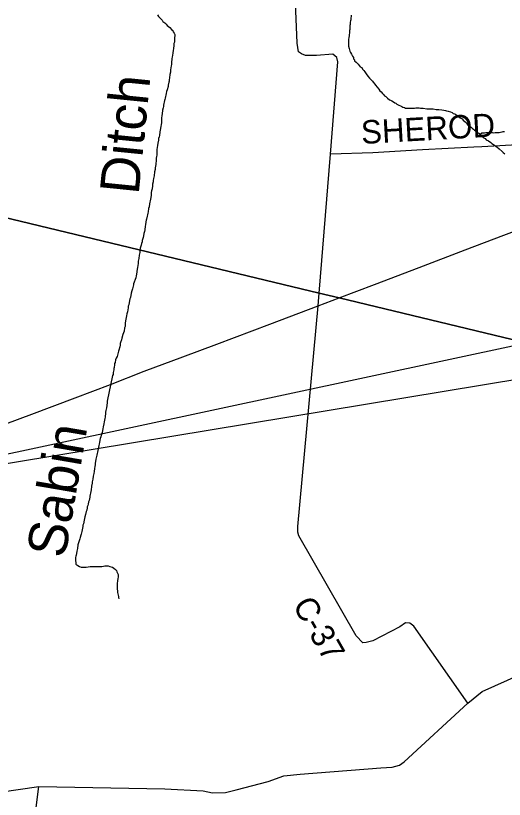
# Model space of a CAD drawing. Extents: x 0.4 to 34.4, y -2.1 to 19.9.
# Drawn here: x 7.097 to 8.281, y 14.658 to 16.558 of the extents above; entities that cross this region are included whole.
import ezdxf

# ---------------------------------------------------------------- set-up
doc = ezdxf.new("R2010")
doc.units = 0
for name, color, linetype in [('GM_X_County_Road', 7, 'Continuous'), ('GM_X_County_Road_Text', 7, 'Continuous'), ('GM_X_Interstate_Route', 7, 'Continuous'), ('GM_X_Minor_River', 7, 'Continuous'), ('GM_X_Minor_River_Text', 7, 'Continuous'), ('GM_X_Township', 7, 'Continuous'), ('GM_X_Township_Road', 7, 'Continuous'), ('GM_X_Township_Road_Text', 7, 'Continuous'), ('SH_Data', 7, 'Continuous')]:
    doc.layers.add(name, color=color, linetype=linetype)

msp = doc.modelspace()

# ---------------------------------------------------------------- linework, layer by layer
at = {"layer": 'GM_X_County_Road'}
for points in [[(7.8306, 15.8648), (7.8323, 15.8856), (7.8597, 16.2224), (7.878, 16.4464), (7.8755, 16.4567), (7.8654, 16.4652), (7.8259, 16.4614), (7.7993, 16.4615), (7.7899, 16.4658), (7.7828, 16.4705), (7.779, 16.4915), (7.7421, 17.3856), (7.739, 17.402), (7.731, 17.4215), (7.7137, 17.448), (7.5422, 17.7657)], [(8.193, 14.8908), (8.0619, 15.0778), (8.0522, 15.0852), (8.042, 15.0854), (8.0278, 15.0758), (7.9626, 15.0421), (7.9462, 15.0379), (7.9382, 15.0373), (7.9226, 15.0546), (7.7835, 15.2967), (7.781, 15.3055), (7.7812, 15.3192), (7.8298, 15.8548), (7.8306, 15.8648), (7.8306, 15.8648)], [(7.058, 14.675), (7.1535, 14.6887), (7.4587, 14.6828), (7.5512, 14.6787), (7.5742, 14.6736), (7.6055, 14.6741), (7.6317, 14.681), (7.709, 14.7012), (7.7472, 14.7146), (7.7868, 14.7187), (7.9822, 14.7342), (8.0096, 14.736), (8.0271, 14.7404), (8.0386, 14.7488), (8.193, 14.8908), (8.2275, 14.9194), (8.32, 14.9606)]]:
    msp.add_lwpolyline(points, dxfattribs=at)
at = {"layer": 'GM_X_Interstate_Route'}
msp.add_lwpolyline([(7.0377, 15.555), (7.1358, 15.592), (7.241, 15.6314), (7.3269, 15.6639), (7.4087, 15.6957), (7.5025, 15.7311), (7.5843, 15.7614), (7.7127, 15.8101), (7.8298, 15.8548), (7.8807, 15.874), (7.967, 15.9065), (8.0753, 15.9471), (8.1867, 15.9903), (8.2799, 16.0261), (8.3601, 16.056)], dxfattribs=at)
at = {"layer": 'GM_X_Minor_River'}
for points in [[(7.4429, 16.5564), (7.4474, 16.5521), (7.4519, 16.5471), (7.4537, 16.5444), (7.4582, 16.5409), (7.462, 16.5377), (7.4642, 16.5343), (7.4672, 16.5323), (7.4705, 16.5292), (7.475, 16.5246), (7.4776, 16.5219), (7.4787, 16.5192), (7.4813, 16.5157), (7.4824, 16.5123), (7.4827, 16.5096), (7.4822, 16.5054), (7.4821, 16.5009), (7.4816, 16.494), (7.4807, 16.4906), (7.4803, 16.4864), (7.4793, 16.4781), (7.4785, 16.4747), (7.4779, 16.4671), (7.4774, 16.4625), (7.4762, 16.4576), (7.4757, 16.4542), (7.4743, 16.4435), (7.4743, 16.4401), (7.4738, 16.4367), (7.4724, 16.4272), (7.4724, 16.4242), (7.4719, 16.4208), (7.4706, 16.4151), (7.4697, 16.4075), (7.4688, 16.4022), (7.4688, 16.3995), (7.4679, 16.3965), (7.4667, 16.39), (7.4662, 16.3866), (7.4645, 16.3787), (7.4629, 16.3745), (7.4616, 16.3696), (7.4591, 16.3582), (7.4586, 16.3552), (7.4578, 16.3522), (7.4553, 16.3412), (7.4552, 16.3381), (7.4544, 16.3347), (7.4527, 16.3294), (7.4517, 16.3199), (7.4513, 16.3161), (7.4504, 16.3097), (7.4503, 16.307), (7.4502, 16.3025), (7.4501, 16.2983), (7.4496, 16.2945), (7.4488, 16.2892), (7.4474, 16.2801), (7.4466, 16.2763), (7.4452, 16.2672), (7.4444, 16.2641), (7.4435, 16.26), (7.4431, 16.2562), (7.4414, 16.2486), (7.4409, 16.2433), (7.4395, 16.2338), (7.4394, 16.2285), (7.4388, 16.2201), (7.4384, 16.2167), (7.4379, 16.2125), (7.4373, 16.2049), (7.4369, 16.2015), (7.4364, 16.1973), (7.4354, 16.189), (7.435, 16.1848), (7.4337, 16.1795), (7.4323, 16.17), (7.4311, 16.1632), (7.4302, 16.1586), (7.4301, 16.1548), (7.4288, 16.1495), (7.4288, 16.1457), (7.4278, 16.1381), (7.4266, 16.1336), (7.4257, 16.129), (7.4252, 16.1222), (7.4238, 16.1131), (7.423, 16.1089), (7.4218, 16.1055), (7.4213, 16.1017), (7.4204, 16.0945), (7.4191, 16.0903), (7.4182, 16.0827), (7.4177, 16.0793), (7.4165, 16.0752), (7.416, 16.0721), (7.4144, 16.0649), (7.4135, 16.0619), (7.4127, 16.0581), (7.4114, 16.0509), (7.4109, 16.0479)], [(7.4411, 16.5602), (7.4429, 16.5564)], [(7.9104, 16.5592), (7.91, 16.5562), (7.9095, 16.5531), (7.909, 16.5482), (7.9086, 16.5456), (7.9081, 16.5425), (7.9077, 16.5395), (7.9076, 16.5368), (7.9072, 16.5342), (7.9067, 16.53), (7.9066, 16.525), (7.9065, 16.5224), (7.9061, 16.5186), (7.906, 16.5155), (7.9056, 16.5125), (7.9055, 16.5091), (7.9046, 16.5053), (7.9041, 16.5004), (7.9041, 16.4969), (7.9036, 16.4928), (7.9035, 16.4897), (7.9035, 16.4867), (7.9038, 16.484), (7.9052, 16.4783), (7.9063, 16.4756), (7.9073, 16.4718), (7.9088, 16.4691), (7.9106, 16.4645), (7.9135, 16.4602), (7.9157, 16.4564), (7.9161, 16.4537), (7.9179, 16.451), (7.9182, 16.4484), (7.9224, 16.4456), (7.9268, 16.4406), (7.9324, 16.4344), (7.9358, 16.4321), (7.938, 16.4286), (7.9406, 16.4248), (7.9432, 16.422), (7.9469, 16.417), (7.9509, 16.4116), (7.955, 16.407), (7.9573, 16.4043), (7.9617, 16.3996), (7.9636, 16.3969), (7.9677, 16.3923), (7.9695, 16.3896), (7.9736, 16.3846), (7.9773, 16.3796), (7.9799, 16.3757), (7.9829, 16.3734), (7.9862, 16.3695), (7.9892, 16.3664), (7.991, 16.3637), (7.9944, 16.3618), (7.9982, 16.3583), (8.003, 16.3544), (8.0057, 16.3532), (8.0087, 16.352), (8.0125, 16.3496), (8.0158, 16.3469), (8.0185, 16.3461), (8.0211, 16.3438), (8.026, 16.341), (8.0298, 16.3394), (8.0332, 16.3375), (8.0358, 16.3363), (8.0392, 16.3351), (8.0418, 16.3339), (8.0457, 16.3338), (8.0498, 16.3337), (8.0525, 16.3337), (8.0559, 16.3336), (8.0586, 16.3339), (8.0636, 16.3342), (8.0666, 16.3346), (8.0701, 16.3345), (8.075, 16.3344), (8.0784, 16.334), (8.0819, 16.3339), (8.0849, 16.3335), (8.0933, 16.3326), (8.0967, 16.3325), (8.1005, 16.3324), (8.1059, 16.3319), (8.1089, 16.3319), (8.1161, 16.331), (8.1188, 16.3309), (8.123, 16.3305), (8.1302, 16.3296), (8.1348, 16.3288), (8.1386, 16.3279), (8.1412, 16.3275), (8.1454, 16.3263), (8.1511, 16.3246), (8.1548, 16.3231), (8.1578, 16.3211), (8.1612, 16.3199), (8.1639, 16.3183), (8.1665, 16.3168)], [(8.1665, 16.3168), (8.1714, 16.3132), (8.1744, 16.3105), (8.1793, 16.3078), (8.1815, 16.3047), (8.1867, 16.3008), (8.189, 16.2981), (8.1923, 16.2942), (8.1957, 16.2919), (8.1987, 16.2892), (8.2017, 16.2872), (8.2039, 16.2845), (8.2069, 16.2829), (8.2095, 16.2802), (8.214, 16.2775), (8.2166, 16.2744), (8.2197, 16.2732), (8.2223, 16.2697), (8.2271, 16.2666), (8.2301, 16.2631), (8.235, 16.2603), (8.2376, 16.2572), (8.2433, 16.2545), (8.2489, 16.2502), (8.2515, 16.2482), (8.2579, 16.2439), (8.2605, 16.2412), (8.2631, 16.2397), (8.2691, 16.2354), (8.2763, 16.2291), (8.2785, 16.2264), (8.283, 16.2229)], [(8.2223, 16.2697), (8.2269, 16.2738), (8.2296, 16.2741), (8.233, 16.2744), (8.2369, 16.2748), (8.2407, 16.2751), (8.2437, 16.275), (8.2464, 16.2746), (8.2502, 16.2745), (8.2529, 16.2745), (8.2559, 16.2744), (8.2594, 16.2747), (8.262, 16.2747), (8.2647, 16.2746), (8.2689, 16.2749), (8.272, 16.276), (8.2762, 16.2763), (8.2789, 16.277), (8.2819, 16.2774)], [(7.4109, 16.0479), (7.41, 16.0391), (7.4091, 16.035), (7.4079, 16.03), (7.4066, 16.024), (7.4057, 16.0198), (7.4033, 16.0126), (7.4032, 16.01), (7.402, 16.0054), (7.4011, 16.0016), (7.399, 15.9941), (7.3982, 15.9884), (7.3977, 15.9842), (7.3972, 15.9808), (7.3964, 15.977), (7.3954, 15.9694), (7.3942, 15.9629), (7.3936, 15.9573), (7.3932, 15.9527), (7.3923, 15.9474), (7.3918, 15.9432), (7.3896, 15.9311), (7.3892, 15.9273), (7.3879, 15.922), (7.3826, 15.908), (7.3822, 15.9053), (7.3801, 15.8955), (7.3784, 15.8909), (7.3772, 15.8856), (7.3754, 15.875), (7.3738, 15.8716), (7.3726, 15.8675), (7.3712, 15.8572), (7.37, 15.8538), (7.3695, 15.8496), (7.3678, 15.8398), (7.3661, 15.8352), (7.3653, 15.8303), (7.3639, 15.822), (7.3631, 15.8178), (7.3626, 15.8128), (7.362, 15.8045), (7.3608, 15.8015), (7.3602, 15.7927), (7.3586, 15.7889), (7.3566, 15.7848), (7.3545, 15.7761), (7.3533, 15.7723), (7.3508, 15.7655), (7.3504, 15.7628), (7.3499, 15.7587), (7.3491, 15.7549), (7.347, 15.7473), (7.3462, 15.7447), (7.3454, 15.7416), (7.3432, 15.7314), (7.3408, 15.7272), (7.3392, 15.7238), (7.3379, 15.7174), (7.3367, 15.7148), (7.3363, 15.7113), (7.3354, 15.7053), (7.3349, 15.7022), (7.3345, 15.6996), (7.3336, 15.6931), (7.3335, 15.6882), (7.3315, 15.6852), (7.3187, 15.6234), (7.3186, 15.6203), (7.3177, 15.6131), (7.3168, 15.6074), (7.3159, 15.601), (7.315, 15.5964), (7.3145, 15.5915), (7.3141, 15.5881), (7.3136, 15.5843), (7.3132, 15.5812), (7.3118, 15.5729), (7.311, 15.568), (7.3089, 15.5608), (7.308, 15.5558), (7.3063, 15.5471), (7.3043, 15.5411), (7.303, 15.5369), (7.3018, 15.5324), (7.3004, 15.5236), (7.2996, 15.5191), (7.2987, 15.5157), (7.2975, 15.5115)], [(7.2975, 15.5115), (7.2958, 15.5036), (7.2953, 15.4998), (7.2941, 15.496), (7.2933, 15.4926), (7.2924, 15.4857), (7.2911, 15.4823), (7.2898, 15.4725), (7.2893, 15.4687), (7.2885, 15.4649), (7.288, 15.4603), (7.287, 15.4527), (7.2862, 15.4482), (7.2853, 15.4448), (7.2849, 15.4417), (7.2836, 15.4338), (7.2831, 15.4311), (7.2827, 15.4277), (7.2822, 15.4246), (7.2805, 15.4171), (7.2805, 15.414), (7.2796, 15.411), (7.2796, 15.4083), (7.2782, 15.4004), (7.2778, 15.3973), (7.2769, 15.3932), (7.2765, 15.3901), (7.2748, 15.3822), (7.2736, 15.3795), (7.2727, 15.3738), (7.2715, 15.3704), (7.2706, 15.3674), (7.2706, 15.3647), (7.2693, 15.359), (7.2681, 15.356), (7.2664, 15.3481), (7.2644, 15.3424), (7.2635, 15.339), (7.2627, 15.3348), (7.2613, 15.3261), (7.2601, 15.3223), (7.2597, 15.3193), (7.2588, 15.3151), (7.2575, 15.3075), (7.2563, 15.3037), (7.2554, 15.3011), (7.255, 15.298), (7.2533, 15.2924), (7.2525, 15.2893), (7.2517, 15.2867), (7.2492, 15.2795), (7.248, 15.2746), (7.2467, 15.2662), (7.2458, 15.2628), (7.2454, 15.2598), (7.2441, 15.2537), (7.2432, 15.2499), (7.2428, 15.2473), (7.2423, 15.2438), (7.2419, 15.2404), (7.2418, 15.237), (7.2424, 15.2313), (7.2431, 15.2282), (7.2473, 15.2247), (7.2518, 15.2224), (7.2559, 15.2211), (7.2609, 15.2207), (7.2639, 15.2206), (7.2678, 15.2209), (7.2727, 15.2216), (7.2773, 15.2223), (7.2815, 15.2222), (7.2846, 15.2221), (7.2888, 15.2224), (7.2914, 15.2224), (7.2956, 15.2223), (7.3002, 15.2226), (7.3029, 15.2226), (7.3055, 15.2225), (7.3101, 15.2232), (7.3128, 15.2239), (7.3155, 15.2239), (7.3182, 15.2242), (7.3212, 15.2238), (7.3254, 15.2225), (7.3284, 15.2217), (7.3318, 15.2205), (7.3352, 15.2186), (7.3386, 15.2154), (7.3412, 15.2124), (7.3422, 15.2097), (7.3441, 15.2062), (7.3455, 15.2031), (7.3455, 15.2005), (7.3454, 15.1974), (7.3445, 15.1921), (7.3441, 15.1887), (7.3436, 15.1857), (7.3432, 15.183), (7.3427, 15.1796), (7.3426, 15.1766)], [(7.3426, 15.1766), (7.3426, 15.1735), (7.3429, 15.1708), (7.3432, 15.1678), (7.3435, 15.1625), (7.3438, 15.159), (7.3445, 15.1563), (7.3452, 15.1529), (7.3459, 15.1499), (7.3462, 15.1472), (7.3472, 15.1437)]]:
    msp.add_lwpolyline(points, dxfattribs=at)
at = {"layer": 'GM_X_Township'}
for points in [[(6.4528, 16.2176), (7.8323, 15.8856), (7.8807, 15.874), (9.5613, 15.4693), (9.5792, 15.465), (9.8001, 15.535)], [(9.8001, 15.535), (9.5792, 15.465), (9.5613, 15.4693), (7.8807, 15.874), (7.8323, 15.8856), (6.4528, 16.2176)]]:
    msp.add_lwpolyline(points, dxfattribs=at)
at = {"layer": 'GM_X_Township_Road'}
for points in [[(8.7188, 16.249), (8.7232, 16.2353), (8.7292, 16.2341), (8.7342, 16.2374), (8.7362, 16.2435), (8.7317, 16.2484), (8.7226, 16.2497), (8.7188, 16.2492), (8.6919, 16.2527), (8.6192, 16.2601), (8.5653, 16.2573), (8.3979, 16.2487), (8.3281, 16.2458), (8.2267, 16.2403), (8.2266, 16.2403)], [(8.2266, 16.2403), (8.2078, 16.2392), (8.0829, 16.2324), (7.9626, 16.2255), (7.8597, 16.2224)], [(6.0486, 13.0593), (6.2023, 13.1806), (6.9275, 13.7533), (6.9437, 13.7644), (6.9532, 13.768), (7.0189, 13.7683), (7.0311, 13.7726), (7.0415, 13.7819), (7.1029, 14.2928), (7.1535, 14.6887)]]:
    msp.add_lwpolyline(points, dxfattribs=at)
at = {"layer": 'SH_Data'}
msp.add_lwpolyline([(10.4047, 16.0223), (10.4047, 16.2068), (6.6239, 15.3979)], close=True, dxfattribs=at)

# ---------------------------------------------------------------- texts
at = {"layer": 'GM_X_County_Road_Text'}
msp.add_text('C-37', height=0.05682, rotation=299.7874, dxfattribs=at).set_placement((7.767, 15.1289))
at = {"layer": 'GM_X_Minor_River_Text'}
for s, height, rotation, p in [('  Ditch', 0.0947, 84.273, (7.3879, 16.0524)), ('Sabin  ', 0.09472, 80.2815, (7.2162, 15.2401))]:
    msp.add_text(s, height=height, rotation=rotation, dxfattribs=at).set_placement(p)
at = {"layer": 'GM_X_Township_Road_Text'}
msp.add_text('SHEROD', height=0.05682, rotation=3.2248, dxfattribs=at).set_placement((7.9357, 16.2469))

doc.saveas('drawing.dxf')
